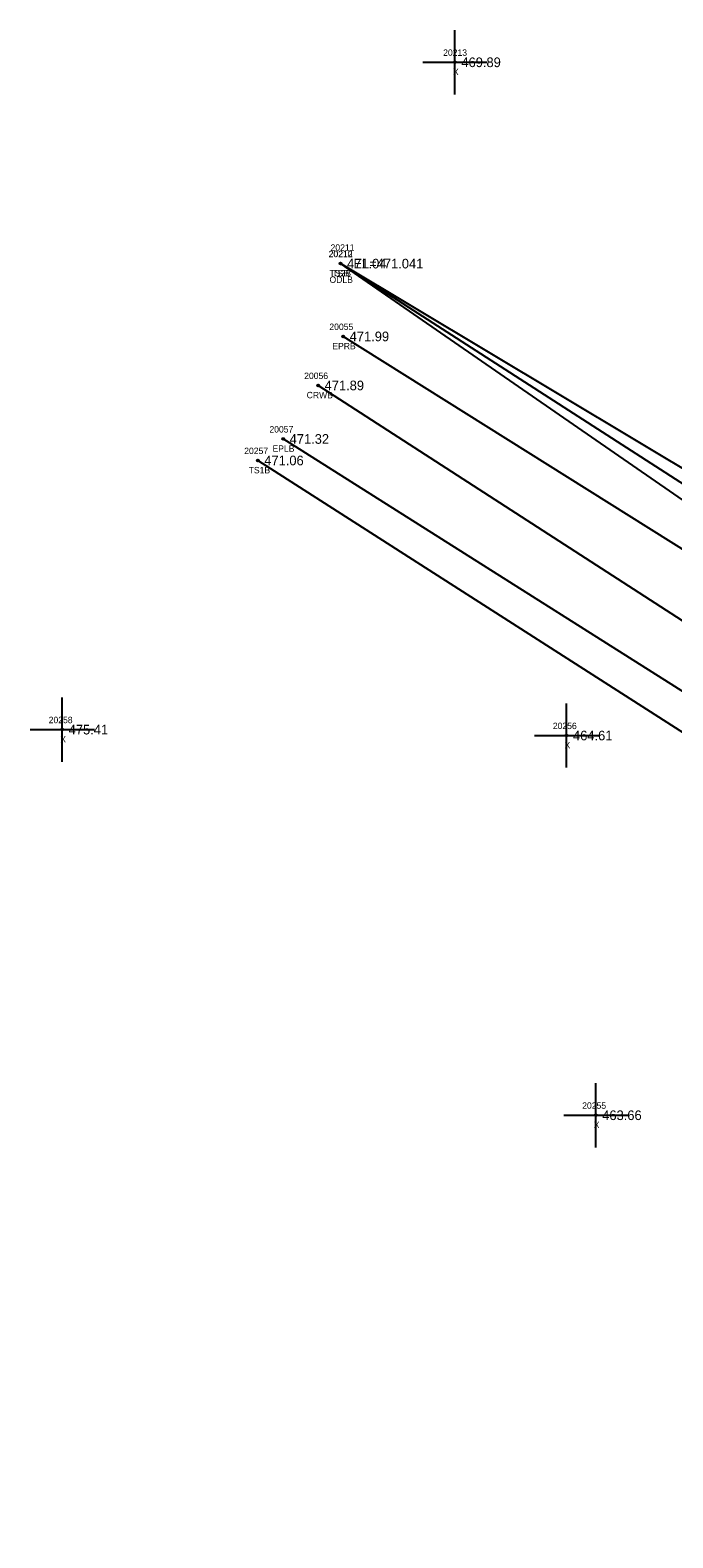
# Model space of a CAD drawing. Extents: x 1797709 to 1799052, y 896018 to 896955.
# Drawn here: x 1797709.4 to 1797809.4, y 896720 to 896954.6 of the extents above; entities that cross this region are included whole.
import ezdxf

# ---------------------------------------------------------------- set-up
doc = ezdxf.new("R2010")
doc.units = 0
for name, color, linetype in [('RD_DTM_BkLn1', 7, 'Continuous'), ('RD_DTM_BkLn2', 7, 'Continuous'), ('RD_DTM_BkLn_txCode', 7, 'Continuous'), ('RD_EX_H2O', 7, 'Continuous'), ('RD_EX_H2O_txCode', 7, 'Continuous'), ('RD_EX_Misc', 7, 'Continuous'), ('RD_EX_Misc_txCode', 7, 'Continuous'), ('RD_EX_Road', 7, 'Continuous'), ('RD_EX_Road_txCode', 7, 'Continuous'), ('RD_EX_TX_H2O_ELEV', 7, 'Continuous'), ('RD_EX_TX_Misc_ELEV', 7, 'Continuous'), ('RD_EX_TX_Road_ELEV', 7, 'Continuous'), ('RD_HC_Survey_ELEV', 7, 'Continuous'), ('RD_HC_Survey_txCode', 7, 'Continuous'), ('RD_SMD_Locator', 7, 'Continuous')]:
    doc.layers.add(name, color=color, linetype=linetype)

msp = doc.modelspace()

# ---------------------------------------------------------------- linework, layer by layer
at = {"layer": 'RD_DTM_BkLn1'}
msp.add_lwpolyline([(1798362.28, 896497.65), (1798275.53, 896555.51), (1798188.06, 896613.78), (1798100.6, 896671.09), (1798012.14, 896729.83), (1797925.7, 896787.19), (1797839.16, 896844.44), (1797754.21, 896899.34)], dxfattribs=at)
at = {"layer": 'RD_DTM_BkLn2'}
for points in [[(1798369.83, 896508.31), (1798367.91, 896513.92), (1798355.6, 896518.28), (1798283.49, 896566.57), (1798194.13, 896625.72), (1798108.66, 896683.13), (1798020.94, 896741.77), (1797934.88, 896798.69), (1797845.83, 896857.42), (1797757.7, 896918.3)], [(1798314.49, 896563.64), (1798288.01, 896573.8), (1798198.07, 896632.21), (1798113.28, 896689.71), (1798026.02, 896748.38), (1797939.51, 896805.48), (1797849.3, 896863.45), (1797757.7, 896918.3)], [(1798355.54, 896486.7), (1798350.74, 896485.38), (1798342.98, 896495.49), (1798267.09, 896545.1), (1798179.21, 896602.99), (1798092.54, 896661.13), (1798003.24, 896719.48), (1797918.21, 896775.43), (1797832.05, 896831.86), (1797744.82, 896887.66)]]:
    msp.add_lwpolyline(points, dxfattribs=at)
at = {"layer": 'RD_EX_H2O'}
msp.add_lwpolyline([(1798314.49, 896563.64), (1798286.18, 896571.49), (1798196.7, 896629.98), (1798111.06, 896686.41), (1798023.38, 896745.41), (1797937.01, 896802.03), (1797847.56, 896860.46), (1797757.7, 896918.3)], dxfattribs=at)
at = {"layer": 'RD_EX_Misc'}
for p, q in [((1797775.5, 896944.63), (1797775.5, 896954.63)), ((1797770.5, 896949.63), (1797780.5, 896949.63)), ((1797714.38, 896840.78), (1797714.38, 896850.78)), ((1797792.87, 896839.86), (1797792.87, 896849.86)), ((1797709.38, 896845.78), (1797719.38, 896845.78)), ((1797787.87, 896844.86), (1797797.87, 896844.86)), ((1797797.42, 896780.77), (1797797.42, 896790.77)), ((1797792.42, 896785.77), (1797802.42, 896785.77))]:
    msp.add_line(p, q, dxfattribs=at)
at = {"layer": 'RD_EX_Road'}
for points in [[(1798362.28, 896497.65), (1798367.54, 896505.07), (1798280.71, 896562.69), (1798193.2, 896621.02), (1798104.98, 896679.23), (1798017.88, 896737.39), (1797930.72, 896795.63), (1797844.07, 896853.07), (1797758.11, 896906.97)], [(1798362.28, 896497.65), (1798357.85, 896490.18), (1798271.29, 896548.71), (1798183.2, 896606.17), (1798096.06, 896663.44), (1798006.57, 896721.75), (1797920.8, 896779.27), (1797834.41, 896836.87), (1797748.77, 896891.01)]]:
    msp.add_lwpolyline(points, dxfattribs=at)
at = {"layer": 'RD_SMD_Locator'}
for centre in [(1797775.5, 896949.63), (1797757.7, 896918.3), (1797757.7, 896918.3), (1797757.7, 896918.3), (1797758.11, 896906.97), (1797754.21, 896899.34), (1797748.77, 896891.01), (1797744.82, 896887.66), (1797714.38, 896845.78), (1797792.87, 896844.86), (1797797.42, 896785.77)]:
    msp.add_circle(centre, 0.15, dxfattribs=at)

# ---------------------------------------------------------------- texts
at = {"layer": 'RD_DTM_BkLn_txCode'}
for s, p in [('20210', (1797755.82, 896919.3)), ('20212', (1797755.86, 896919.3)), ('TS2B', (1797755.98, 896916.3)), ('TSB', (1797756.43, 896916.3)), ('20257', (1797742.7, 896888.66)), ('TS1B', (1797743.39, 896885.66))]:
    msp.add_text(s, height=1, dxfattribs=at).set_placement(p)
at = {"layer": 'RD_EX_H2O_txCode'}
for s, p in [('20211', (1797756.14, 896920.3)), ('ODLB', (1797755.98, 896915.3))]:
    msp.add_text(s, height=1, dxfattribs=at).set_placement(p)
at = {"layer": 'RD_EX_Misc_txCode'}
for s, p in [('20213', (1797773.66, 896950.63)), ('X', (1797775.18, 896947.63)), ('20258', (1797712.27, 896846.78)), ('20256', (1797790.73, 896845.86)), ('X', (1797714.07, 896843.78)), ('X', (1797792.55, 896842.86)), ('20255', (1797795.3, 896786.77)), ('X', (1797797.1, 896783.77))]:
    msp.add_text(s, height=1, dxfattribs=at).set_placement(p)
at = {"layer": 'RD_EX_Road_txCode'}
for s, p in [('20055', (1797755.95, 896907.97)), ('EPRB', (1797756.41, 896904.97)), ('20057', (1797746.62, 896892.01)), ('EPLB', (1797747.1, 896889.01))]:
    msp.add_text(s, height=1, dxfattribs=at).set_placement(p)
at = {"layer": 'RD_EX_TX_H2O_ELEV'}
msp.add_text('EL=471.041', height=1.5, dxfattribs=at).set_placement((1797759.7, 896917.55))
at = {"layer": 'RD_EX_TX_Misc_ELEV'}
for s, p in [('469.89', (1797776.5, 896948.88)), ('471.04', (1797758.7, 896917.55)), ('471.04', (1797758.7, 896917.55)), ('471.06', (1797745.82, 896886.91)), ('475.41', (1797715.38, 896845.03)), ('464.61', (1797793.87, 896844.11)), ('463.66', (1797798.42, 896785.02))]:
    msp.add_text(s, height=1.5, dxfattribs=at).set_placement(p)
at = {"layer": 'RD_EX_TX_Road_ELEV'}
for s, p in [('471.99', (1797759.11, 896906.22)), ('471.32', (1797749.77, 896890.26))]:
    msp.add_text(s, height=1.5, dxfattribs=at).set_placement(p)
at = {"layer": 'RD_HC_Survey_ELEV'}
msp.add_text('471.89', height=1.5, dxfattribs=at).set_placement((1797755.21, 896898.59))
at = {"layer": 'RD_HC_Survey_txCode'}
for s, p in [('20056', (1797752.03, 896900.34)), ('CRWB', (1797752.42, 896897.34))]:
    msp.add_text(s, height=1, dxfattribs=at).set_placement(p)

doc.saveas('drawing.dxf')
